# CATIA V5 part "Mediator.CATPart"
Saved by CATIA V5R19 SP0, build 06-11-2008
Part number: Mediator
Material "Plastique": density 1200 kg/m3, Young's modulus 2.2e+09 Pa, Poisson ratio 0.38, thermal expansion 6.84e-05 1/K
Bounding box of the stored display mesh (mm): x -14.597 to 14.604, y 0 to 1, z -2.446 to 29.408
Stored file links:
  I:\mediator\Mediator.CATPart
  C:\Program Files (x86)\Dassault Systemes\B19\intel_a\startup\materials\French\Catalog.CATMaterial
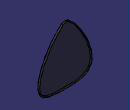
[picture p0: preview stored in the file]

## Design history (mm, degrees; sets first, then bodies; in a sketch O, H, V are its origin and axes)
Body1 (main body), material "Plastique"
  Sketch1 on zx-plane, origin (0, 0, 0), H (-1, 0, 0), V (0, 0, 1)
    point P1 (-12.5, 0.0247)
    point P2 (0, 30.0247)
    spline S1 through (0, 30.0247) (-7.3, 23) (-12.5, 0.0247) (0.0036, -2.52) (12.5, 0.0247) (7.3, 23) (0, 30.0247)
    arc A1 centre (0, 26.3274) radius 3.0804 from (1.8791, 28.7683) to (-1.8791, 28.7683) ccw
    point P3 (0, 26.3274)
    point P4 (1.8791, 28.7683)
    point P6 (-1.8791, 28.7683)
    point P7 (-1.8791, 28.7683)
    point P8 (0, 30.0247)
    point P10 (0, 30.0247)
    point P11 (-12.5, 0.0247)
    point P12 (7.3, 23)
    point P13 (-7.3, 23)
    distance P1 V = 12.5
    distance P2 V = 0
    distance P11 P1 = 0
    distance P12 V = 7.3
    distance V P13 = 7.3
    distance P12 H = 23
    distance H P13 = 23
    distance A1 S1 = 0
    coincidence: P8 P2, P10 P2, P3 V, A1 P4, P4 S1, A1 P6, S1 P7, P6 P7
  Pad1: profile Sketch1, direction (0, 1, 0), length 1
  Fillet1: radius 0.5, on end face of Pad1
  Fillet2: radius 0.5, on start face of Pad1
